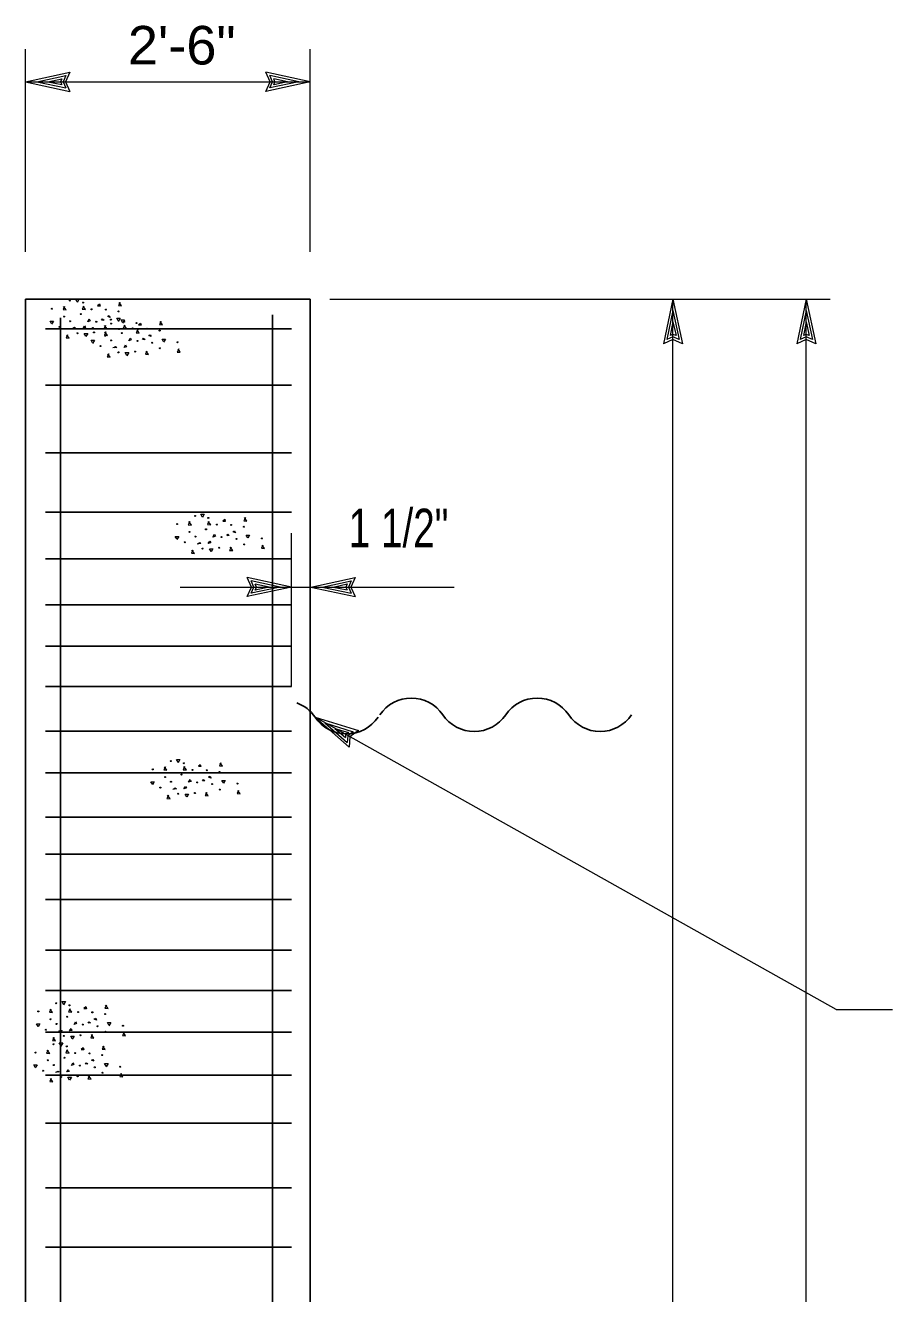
# Model space of a CAD drawing. Extents: x -28.1 to 13.9, y -16.1 to 13.9.
# Drawn here: x -2.228 to 0.583, y 7.352 to 11.464 of the extents above; entities that cross this region are included whole.
import ezdxf
from ezdxf.enums import TextEntityAlignment as Align

# ---------------------------------------------------------------- set-up
doc = ezdxf.new("R2010")
doc.units = 0
doc.header["$LTSCALE"] = 0.05
doc.layers.add('1', color=7, linetype='Continuous', lineweight=13)
doc.layers.add('2', color=7, linetype='Continuous', lineweight=13)

msp = doc.modelspace()

# ---------------------------------------------------------------- linework, layer by layer
at = {"layer": '1'}
for p, q in [((-2.22804, 10.72969), (-2.22804, 11.38669)), ((-1.30504, 10.72969), (-1.30504, 11.38669)), ((-2.22804, 11.28069), (-2.08404, 11.31169)), ((-1.30504, 11.28069), (-1.44904, 11.31169)), ((-2.22804, 11.28069), (-1.30504, 11.28069)), ((-2.22804, 11.28069), (-2.08404, 11.24969)), ((-2.19104, 11.28069), (-2.09704, 11.30069)), ((-2.19104, 11.28069), (-2.09704, 11.26069)), ((-2.15504, 11.28069), (-2.11004, 11.29069)), ((-2.15504, 11.28069), (-2.11004, 11.27169)), ((-2.11004, 11.29069), (-2.11404, 11.28069)), ((-2.11404, 11.28069), (-2.11004, 11.27169)), ((-2.09704, 11.30069), (-2.10604, 11.28069)), ((-2.10604, 11.28069), (-2.09704, 11.26069)), ((-1.30504, 11.28069), (-1.44904, 11.24969)), ((-1.34204, 11.28069), (-1.43604, 11.30069)), ((-1.42704, 11.28069), (-1.43604, 11.30069)), ((-1.34204, 11.28069), (-1.43604, 11.26069)), ((-1.43604, 11.26069), (-1.42704, 11.28069)), ((-1.37804, 11.28069), (-1.42304, 11.28969)), ((-1.41904, 11.28069), (-1.42304, 11.28969)), ((-1.37804, 11.28069), (-1.42304, 11.27069)), ((-1.42304, 11.27069), (-1.41904, 11.28069)), ((-1.24104, 10.57569), (0.37996, 10.57569)), ((-0.12904, 10.57569), (-0.16004, 10.43169)), ((-0.12904, 10.57569), (-0.09804, 10.43169)), ((0.30296, 10.57569), (0.27196, 10.43169)), ((0.30296, 3.07869), (0.30296, 10.57569)), ((0.30296, 10.57569), (0.33396, 10.43169)), ((-0.12904, 10.53869), (-0.14904, 10.44469)), ((-0.12904, 10.53869), (-0.10904, 10.44469)), ((0.30296, 10.53869), (0.28296, 10.44469)), ((0.30296, 10.53869), (0.32296, 10.44469)), ((-0.12904, 10.50269), (-0.13804, 10.45769)), ((-0.12904, 10.50269), (-0.11904, 10.45769)), ((0.30296, 10.50269), (0.29396, 10.45769)), ((0.30296, 10.50269), (0.31296, 10.45769)), ((-0.12904, 10.45369), (-0.14904, 10.44469)), ((-0.12904, 10.46169), (-0.13804, 10.45769)), ((-0.11904, 10.45769), (-0.12904, 10.46169)), ((-0.10904, 10.44469), (-0.12904, 10.45369)), ((0.30296, 10.45369), (0.28296, 10.44469)), ((0.30296, 10.46169), (0.29396, 10.45769)), ((0.31296, 10.45769), (0.30296, 10.46169)), ((0.32296, 10.44469), (0.30296, 10.45369)), ((-1.36504, 9.32069), (-1.36504, 9.81769)), ((-1.36504, 9.64269), (-1.50904, 9.67369)), ((-1.40204, 9.64269), (-1.49604, 9.66269)), ((-1.48704, 9.64269), (-1.49604, 9.66269)), ((-1.30304, 9.64269), (-1.15904, 9.67369)), ((-1.26604, 9.64269), (-1.17204, 9.66269)), ((-1.17204, 9.66269), (-1.18104, 9.64269)), ((-1.36504, 9.64269), (-1.50904, 9.61169)), ((-1.40204, 9.64269), (-1.49604, 9.62269)), ((-1.49604, 9.62269), (-1.48704, 9.64269)), ((-1.43804, 9.64269), (-1.48304, 9.65169)), ((-1.47904, 9.64269), (-1.48304, 9.65169)), ((-1.43804, 9.64269), (-1.48304, 9.63269)), ((-1.48304, 9.63269), (-1.47904, 9.64269)), ((-1.30304, 9.64269), (-1.15904, 9.61169)), ((-1.26604, 9.64269), (-1.17204, 9.62269)), ((-1.23004, 9.64269), (-1.18504, 9.65269)), ((-1.23004, 9.64269), (-1.18504, 9.63369)), ((-1.18504, 9.65269), (-1.18904, 9.64269)), ((-1.18904, 9.64269), (-1.18504, 9.63369)), ((-1.18104, 9.64269), (-1.17204, 9.62269)), ((-1.28904, 9.22069), (-1.17904, 9.12369)), ((-1.25704, 9.20269), (-1.16504, 9.17369)), ((-1.25704, 9.20269), (-1.18504, 9.13869)), ((-1.22504, 9.18469), (-1.19004, 9.15469)), ((-1.22504, 9.18469), (-1.18104, 9.17169)), ((-1.18104, 9.17169), (-1.19004, 9.16469)), ((-1.16504, 9.17369), (-1.18304, 9.16069)), ((-1.19004, 9.16469), (-1.19004, 9.15469)), ((-1.18304, 9.16069), (-1.18504, 9.13869)), ((0.39996, 8.27369), (0.58296, 8.27369))]:
    msp.add_line(p, q, dxfattribs=at)
at = {"layer": '1', "lineweight": 25}
for p, q in [((-2.22804, 4.01169), (-2.22804, 10.57569)), ((-2.22804, 10.57569), (-1.30504, 10.57569)), ((-1.30504, 3.64169), (-1.30504, 10.57569)), ((-2.11404, 3.16869), (-2.11404, 10.51569)), ((-1.42704, 3.16369), (-1.42704, 10.52469)), ((-2.16304, 10.47969), (-1.36504, 10.47969)), ((-2.16304, 10.29669), (-1.36504, 10.29669)), ((-2.16304, 10.07769), (-1.36504, 10.07769)), ((-2.16304, 9.88569), (-1.36504, 9.88569)), ((-2.16304, 9.73369), (-1.36504, 9.73369)), ((-2.16304, 9.58469), (-1.36504, 9.58469)), ((-2.16304, 9.45069), (-1.36504, 9.45069)), ((-2.16304, 9.32069), (-1.36504, 9.32069)), ((-2.16304, 9.17569), (-1.36504, 9.17569)), ((-2.16304, 9.04069), (-1.36504, 9.04069)), ((-2.16304, 8.89669), (-1.36504, 8.89669)), ((-2.16304, 8.77669), (-1.36504, 8.77669)), ((-2.16304, 8.62969), (-1.36504, 8.62969)), ((-2.16304, 8.46569), (-1.36504, 8.46569)), ((-2.16304, 8.33469), (-1.36504, 8.33469)), ((-2.16304, 8.19969), (-1.36504, 8.19969)), ((-2.16304, 8.06069), (-1.36504, 8.06069)), ((-2.16304, 7.90469), (-1.36504, 7.90469)), ((-2.16304, 7.69569), (-1.36504, 7.69569)), ((-2.16304, 7.50269), (-1.36504, 7.50269))]:
    msp.add_line(p, q, dxfattribs=at)
at = {"layer": '1'}
for points in [[(-2.08404, 11.31169), (-2.09804, 11.28069), (-2.08404, 11.24969)], [(-1.44904, 11.24969), (-1.43504, 11.28069), (-1.44904, 11.31169)], [(-0.12904, 3.07869), (-0.12904, 4.00669), (-0.12904, 10.57569)], [(-0.09804, 10.43169), (-0.12904, 10.44569), (-0.16004, 10.43169)], [(0.33396, 10.43169), (0.30296, 10.44569), (0.27196, 10.43169)], [(-1.50904, 9.61169), (-1.49504, 9.64269), (-1.50904, 9.67369)], [(-1.15904, 9.67369), (-1.17304, 9.64269), (-1.15904, 9.61169)], [(-1.72604, 9.64269), (-1.36504, 9.64269), (-1.30304, 9.64269), (-0.83804, 9.64269)], [(0.39996, 8.27369), (-1.28904, 9.22069), (-1.14804, 9.17769)], [(-1.14804, 9.17769), (-1.17604, 9.15669), (-1.17904, 9.12369)]]:
    msp.add_lwpolyline(points, dxfattribs=at)
at = {"layer": '1', "lineweight": 25}
for centre, start, end in [((-1.39104, 9.15169), 34.0772, 69.6384), ((-0.97704, 9.15969), 34.0772, 145.92281), ((-0.56904, 9.15969), 34.0772, 145.92281), ((-1.18704, 9.28969), 214.0772, 325.92281), ((-0.77304, 9.29769), 214.0772, 325.92281), ((-0.36504, 9.29769), 214.0772, 325.92281)]:
    msp.add_arc(centre, 0.12315, start, end, dxfattribs=at)
at = {"layer": '2'}
for p, q in [((-1.99404, 10.55569), (-1.98804, 10.56069)), ((-1.86104, 10.49369), (-1.85504, 10.49869)), ((-1.58804, 9.85769), (-1.58204, 9.86269)), ((-1.66704, 9.06269), (-1.66104, 9.06769)), ((-2.03804, 8.27769), (-2.03204, 8.28269)), ((-2.04704, 8.14469), (-2.04104, 8.14969))]:
    msp.add_line(p, q, dxfattribs=at)
for points in [[(-2.06004, 10.56769), (-2.06504, 10.57669), (-2.05404, 10.57669), (-2.06004, 10.56569)], [(-2.10104, 10.55269), (-2.10604, 10.54269), (-2.09604, 10.54169), (-2.10404, 10.55269)], [(-2.03904, 10.55369), (-2.04404, 10.54369), (-2.03304, 10.54269), (-2.04104, 10.55369)], [(-1.98804, 10.56069), (-1.98604, 10.55369), (-1.99404, 10.55369)], [(-1.92104, 10.56569), (-1.92604, 10.55569), (-1.91604, 10.55469), (-1.92404, 10.56569)], [(-2.14304, 10.49669), (-2.14804, 10.50469), (-2.13704, 10.50469), (-2.14304, 10.49469)], [(-2.07404, 10.48169), (-2.06904, 10.48469), (-2.06504, 10.48169), (-2.07704, 10.47969)], [(-1.98104, 10.50769), (-1.97804, 10.51169), (-1.97304, 10.50769), (-1.98004, 10.50669)], [(-1.96804, 10.49069), (-1.97304, 10.48069), (-1.96304, 10.47969), (-1.97104, 10.49069)], [(-1.96104, 10.52069), (-1.95604, 10.52269), (-1.95304, 10.51669), (-1.96104, 10.51969)], [(-1.92704, 10.50569), (-1.93204, 10.51469), (-1.92104, 10.51469), (-1.92704, 10.50369)], [(-1.91304, 10.50069), (-1.91804, 10.50869), (-1.90704, 10.50869), (-1.91304, 10.49869)], [(-1.90604, 10.49169), (-1.91104, 10.48169), (-1.90004, 10.48069), (-1.90804, 10.49169)], [(-1.85504, 10.49869), (-1.85304, 10.49169), (-1.86104, 10.49169)], [(-1.78804, 10.50369), (-1.79304, 10.49369), (-1.78304, 10.49269), (-1.79104, 10.50369)], [(-2.09104, 10.46069), (-2.09604, 10.45069), (-2.08604, 10.44969), (-2.09404, 10.46069)], [(-2.03204, 10.45569), (-2.03704, 10.46469), (-2.02604, 10.46469), (-2.03204, 10.45469)], [(-1.96704, 10.46969), (-1.97204, 10.45969), (-1.96204, 10.45869), (-1.97004, 10.46969)], [(-1.86404, 10.47669), (-1.86904, 10.46669), (-1.85904, 10.46569), (-1.86604, 10.47669)], [(-1.84804, 10.44569), (-1.84504, 10.44969), (-1.84004, 10.44569), (-1.84704, 10.44469)], [(-1.82804, 10.45869), (-1.82304, 10.46069), (-1.82004, 10.45469), (-1.82804, 10.45769)], [(-1.78004, 10.43869), (-1.78504, 10.44669), (-1.77404, 10.44669), (-1.78004, 10.43669)], [(-2.01004, 10.43469), (-2.01504, 10.44269), (-2.00404, 10.44269), (-2.01004, 10.43269)], [(-1.94104, 10.41969), (-1.93604, 10.42269), (-1.93204, 10.41969), (-1.94404, 10.41769)], [(-1.89904, 10.39369), (-1.90404, 10.40269), (-1.89304, 10.40269), (-1.89904, 10.39269)], [(-1.83404, 10.40769), (-1.83904, 10.39769), (-1.82904, 10.39669), (-1.83704, 10.40769)], [(-1.73104, 10.41469), (-1.73604, 10.40469), (-1.72604, 10.40369), (-1.73304, 10.41469)], [(-1.95804, 10.39869), (-1.96304, 10.38869), (-1.95304, 10.38769), (-1.96104, 10.39869)], [(-1.65404, 9.86969), (-1.65904, 9.87869), (-1.64804, 9.87869), (-1.65404, 9.86769)], [(-1.51504, 9.86769), (-1.52004, 9.85769), (-1.51004, 9.85669), (-1.51804, 9.86769)], [(-1.69504, 9.85469), (-1.70004, 9.84469), (-1.69004, 9.84369), (-1.69804, 9.85469)], [(-1.63304, 9.85569), (-1.63804, 9.84569), (-1.62704, 9.84469), (-1.63504, 9.85569)], [(-1.58204, 9.86269), (-1.58004, 9.85569), (-1.58804, 9.85569)], [(-1.73704, 9.79869), (-1.74204, 9.80669), (-1.73104, 9.80669), (-1.73704, 9.79669)], [(-1.66804, 9.78369), (-1.66304, 9.78669), (-1.65904, 9.78369), (-1.67104, 9.78169)], [(-1.57504, 9.80969), (-1.57204, 9.81369), (-1.56704, 9.80969), (-1.57404, 9.80869)], [(-1.55504, 9.82269), (-1.55004, 9.82469), (-1.54704, 9.81869), (-1.55504, 9.82169)], [(-1.50704, 9.80269), (-1.51204, 9.81069), (-1.50104, 9.81069), (-1.50704, 9.80069)], [(-1.68504, 9.76269), (-1.69004, 9.75269), (-1.68004, 9.75169), (-1.68804, 9.76269)], [(-1.62604, 9.75769), (-1.63104, 9.76669), (-1.62004, 9.76669), (-1.62604, 9.75669)], [(-1.56104, 9.77169), (-1.56604, 9.76169), (-1.55604, 9.76069), (-1.56404, 9.77169)], [(-1.45804, 9.77869), (-1.46304, 9.76869), (-1.45304, 9.76769), (-1.46004, 9.77869)], [(-1.77404, 9.05969), (-1.77904, 9.04969), (-1.76904, 9.04869), (-1.77704, 9.05969)], [(-1.73304, 9.07469), (-1.73804, 9.08369), (-1.72704, 9.08369), (-1.73304, 9.07269)], [(-1.71204, 9.06069), (-1.71704, 9.05069), (-1.70604, 9.04969), (-1.71404, 9.06069)], [(-1.66104, 9.06769), (-1.65904, 9.06069), (-1.66704, 9.06069)], [(-1.59404, 9.07269), (-1.59904, 9.06269), (-1.58904, 9.06169), (-1.59704, 9.07269)], [(-1.81604, 9.00369), (-1.82104, 9.01169), (-1.81004, 9.01169), (-1.81604, 9.00169)], [(-1.65404, 9.01469), (-1.65104, 9.01869), (-1.64604, 9.01469), (-1.65304, 9.01369)], [(-1.63404, 9.02769), (-1.62904, 9.02969), (-1.62604, 9.02369), (-1.63404, 9.02669)], [(-1.58604, 9.00769), (-1.59104, 9.01569), (-1.58004, 9.01569), (-1.58604, 9.00569)], [(-1.76404, 8.96769), (-1.76904, 8.95769), (-1.75904, 8.95669), (-1.76704, 8.96769)], [(-1.74704, 8.98869), (-1.74204, 8.99169), (-1.73804, 8.98869), (-1.75004, 8.98669)], [(-1.70504, 8.96269), (-1.71004, 8.97169), (-1.69904, 8.97169), (-1.70504, 8.96169)], [(-1.64004, 8.97669), (-1.64504, 8.96669), (-1.63504, 8.96569), (-1.64304, 8.97669)], [(-1.53704, 8.98369), (-1.54204, 8.97369), (-1.53204, 8.97269), (-1.53904, 8.98369)], [(-2.14504, 8.27469), (-2.15004, 8.26469), (-2.14004, 8.26369), (-2.14804, 8.27469)], [(-2.10404, 8.28969), (-2.10904, 8.29869), (-2.09804, 8.29869), (-2.10404, 8.28769)], [(-2.08304, 8.27569), (-2.08804, 8.26569), (-2.07704, 8.26469), (-2.08504, 8.27569)], [(-2.03204, 8.28269), (-2.03004, 8.27569), (-2.03804, 8.27569)], [(-1.96504, 8.28769), (-1.97004, 8.27769), (-1.96004, 8.27669), (-1.96804, 8.28769)], [(-2.18704, 8.21869), (-2.19204, 8.22669), (-2.18104, 8.22669), (-2.18704, 8.21669)], [(-2.02504, 8.22969), (-2.02204, 8.23369), (-2.01704, 8.22969), (-2.02404, 8.22869)], [(-2.00504, 8.24269), (-2.00004, 8.24469), (-1.99704, 8.23869), (-2.00504, 8.24169)], [(-1.95704, 8.22269), (-1.96204, 8.23069), (-1.95104, 8.23069), (-1.95704, 8.22069)], [(-2.13504, 8.18269), (-2.14004, 8.17269), (-2.13004, 8.17169), (-2.13804, 8.18269)], [(-2.11804, 8.20369), (-2.11304, 8.20669), (-2.10904, 8.20369), (-2.12104, 8.20169)], [(-2.07604, 8.17769), (-2.08104, 8.18669), (-2.07004, 8.18669), (-2.07604, 8.17669)], [(-2.01104, 8.19169), (-2.01604, 8.18169), (-2.00604, 8.18069), (-2.01404, 8.19169)], [(-1.90804, 8.19869), (-1.91304, 8.18869), (-1.90304, 8.18769), (-1.91004, 8.19869)], [(-2.15404, 8.14169), (-2.15904, 8.13169), (-2.14904, 8.13069), (-2.15704, 8.14169)], [(-2.11304, 8.15669), (-2.11804, 8.16569), (-2.10704, 8.16569), (-2.11304, 8.15469)], [(-2.09204, 8.14269), (-2.09704, 8.13269), (-2.08604, 8.13169), (-2.09404, 8.14269)], [(-2.04104, 8.14969), (-2.03904, 8.14269), (-2.04704, 8.14269)], [(-1.97404, 8.15469), (-1.97904, 8.14469), (-1.96904, 8.14369), (-1.97704, 8.15469)], [(-2.03404, 8.09669), (-2.03104, 8.10069), (-2.02604, 8.09669), (-2.03304, 8.09569)], [(-2.01404, 8.10969), (-2.00904, 8.11169), (-2.00604, 8.10569), (-2.01404, 8.10869)], [(-2.19604, 8.08569), (-2.20104, 8.09369), (-2.19004, 8.09369), (-2.19604, 8.08369)], [(-2.12704, 8.07069), (-2.12204, 8.07369), (-2.11804, 8.07069), (-2.13004, 8.06869)], [(-2.02004, 8.05869), (-2.02504, 8.04869), (-2.01504, 8.04769), (-2.02304, 8.05869)], [(-1.96604, 8.08969), (-1.97104, 8.09769), (-1.96004, 8.09769), (-1.96604, 8.08769)], [(-1.91704, 8.06569), (-1.92204, 8.05569), (-1.91204, 8.05469), (-1.91904, 8.06569)], [(-2.14404, 8.04969), (-2.14904, 8.03969), (-2.13904, 8.03869), (-2.14704, 8.04969)], [(-2.08504, 8.04469), (-2.09004, 8.05369), (-2.07904, 8.05369), (-2.08504, 8.04369)]]:
    msp.add_lwpolyline(points, dxfattribs=at)
for points in [[(-2.04104, 10.48169), (-2.03604, 10.48969), (-2.03304, 10.48369)], [(-2.02604, 10.50269), (-2.02104, 10.51169), (-2.01804, 10.50569)], [(-1.89304, 10.44069), (-1.88804, 10.44969), (-1.88504, 10.44369)], [(-1.90804, 10.41969), (-1.90304, 10.42769), (-1.90004, 10.42169)], [(-1.63504, 9.78369), (-1.63004, 9.79169), (-1.62704, 9.78569)], [(-1.62004, 9.80469), (-1.61504, 9.81369), (-1.61204, 9.80769)], [(-1.69904, 9.00969), (-1.69404, 9.01869), (-1.69104, 9.01269)], [(-1.71404, 8.98869), (-1.70904, 8.99669), (-1.70604, 8.99069)], [(-2.07004, 8.22469), (-2.06504, 8.23369), (-2.06204, 8.22769)], [(-2.08504, 8.20369), (-2.08004, 8.21169), (-2.07704, 8.20569)], [(-2.07904, 8.09169), (-2.07404, 8.10069), (-2.07104, 8.09469)], [(-2.09404, 8.07069), (-2.08904, 8.07869), (-2.08604, 8.07269)]]:
    msp.add_lwpolyline(points, close=True, dxfattribs=at)
for centre in [(-2.08379, 10.57156), (-2.04104, 10.56481), (-2.14204, 10.54481), (-2.04854, 10.52781), (-2.01329, 10.54306), (-1.96704, 10.54206), (-1.92579, 10.53631), (-2.11754, 10.48581), (-2.10229, 10.51956), (-2.08304, 10.50431), (-2.00904, 10.48281), (-1.99804, 10.50256), (-1.95079, 10.50956), (-1.95004, 10.49681), (-1.90804, 10.50281), (-1.86754, 10.49856), (-2.05954, 10.46556), (-2.00554, 10.46806), (-1.96929, 10.45756), (-1.95004, 10.44231), (-1.92479, 10.47906), (-1.91554, 10.46581), (-1.88029, 10.48106), (-1.83404, 10.48006), (-1.79279, 10.47431), (-1.98454, 10.42381), (-1.92654, 10.40356), (-1.87254, 10.40606), (-1.86504, 10.44056), (-1.81704, 10.43481), (-1.79179, 10.41706), (-1.73454, 10.43656), (-1.67779, 9.87356), (-1.63504, 9.86681), (-1.73604, 9.84681), (-1.64254, 9.82981), (-1.60729, 9.84506), (-1.56104, 9.84406), (-1.51979, 9.83831), (-1.71154, 9.78781), (-1.69629, 9.82156), (-1.67704, 9.80631), (-1.59204, 9.80456), (-1.54404, 9.79881), (-1.46154, 9.80056), (-1.65354, 9.76756), (-1.59954, 9.77006), (-1.51879, 9.78106), (-1.81504, 9.05181), (-1.75679, 9.07856), (-1.71404, 9.07181), (-1.68629, 9.05006), (-1.64004, 9.04906), (-1.77529, 9.02656), (-1.75604, 9.01131), (-1.72154, 9.03481), (-1.67104, 9.00956), (-1.62304, 9.00381), (-1.59879, 9.04331), (-1.54054, 9.00556), (-1.79054, 8.99281), (-1.73254, 8.97256), (-1.67854, 8.97506), (-1.59779, 8.98606), (-2.18604, 8.26681), (-2.12779, 8.29356), (-2.08504, 8.28681), (-2.05729, 8.26506), (-2.01104, 8.26406), (-2.14629, 8.24156), (-2.12704, 8.22631), (-2.09254, 8.24981), (-2.04204, 8.22456), (-1.96979, 8.25831), (-2.16154, 8.20781), (-2.10354, 8.18756), (-2.04954, 8.19006), (-1.99404, 8.21881), (-1.96879, 8.20106), (-1.91154, 8.22056), (-2.13679, 8.16056), (-2.09404, 8.15381), (-2.19504, 8.13381), (-2.15529, 8.10856), (-2.10154, 8.11681), (-2.06629, 8.13206), (-2.02004, 8.13106), (-1.97879, 8.12531), (-2.17054, 8.07481), (-2.13604, 8.09331), (-2.05854, 8.05706), (-2.05104, 8.09156), (-2.00304, 8.08581), (-1.97779, 8.06806), (-1.92054, 8.08756), (-2.11254, 8.05456)]:
    msp.add_circle(centre, 0.00162, dxfattribs=at)

# ---------------------------------------------------------------- texts
at = {"layer": '1', "width": 1.05}
msp.add_text('2\'-6"', height=0.125, dxfattribs=at).set_placement((-1.72116, 11.33669), align=Align.CENTER)
at = {"layer": '1', "width": 0.75}
msp.add_text('1 1/2"', height=0.125, dxfattribs=at).set_placement((-1.18004, 9.77169))

doc.saveas('drawing.dxf')
